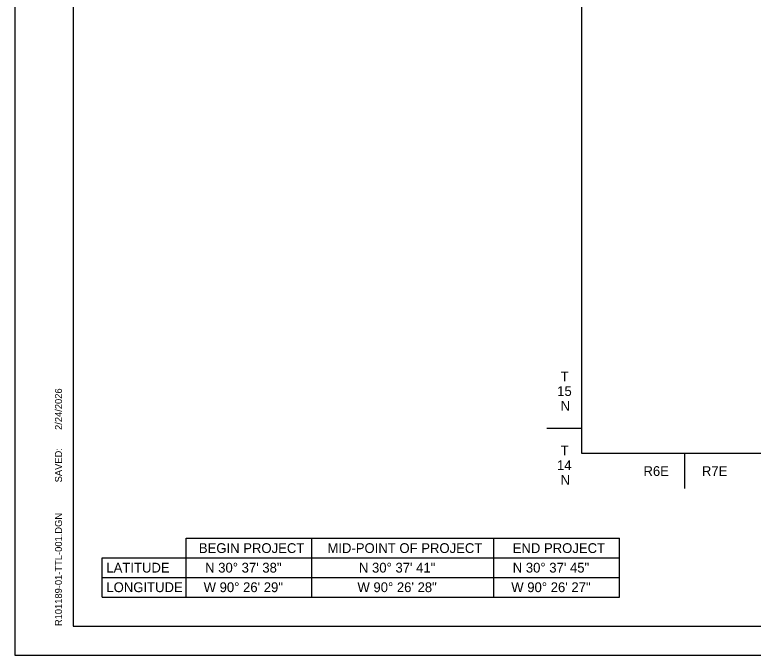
# Model space of a CAD drawing. Extents: x -0.54 to 1.64, y 0 to 0.92.
# Drawn here: x 0 to 0.528, y 0 to 0.458 of the extents above; entities that cross this region are included whole.
import ezdxf

# ---------------------------------------------------------------- set-up
doc = ezdxf.new("R2010")
doc.units = 0
for name, color, linetype in [('DSN_DRFT_DNC', 7, 'Continuous'), ('SHET_Annotations', 7, 'Continuous'), ('SHET_Border-Lines', 7, 'Continuous'), ('SHET_Border-Text', 7, 'Continuous')]:
    doc.layers.add(name, color=color, linetype=linetype)

msp = doc.modelspace()

# ---------------------------------------------------------------- linework, layer by layer
at = {"layer": 'DSN_DRFT_DNC'}
msp.add_lwpolyline([(0.4056037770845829, 0.541666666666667), (1.052729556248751, 0.541666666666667), (1.052729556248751, 0.14429633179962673), (0.4056037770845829, 0.14429633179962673)], close=True, dxfattribs=at)
at = {"layer": 'SHET_Annotations'}
for p, q in [((0.3806037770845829, 0.16250892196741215), (0.4056037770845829, 0.16250892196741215)), ((0.47890184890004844, 0.14429633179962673), (0.47890305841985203, 0.11929633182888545))]:
    msp.add_line(p, q, dxfattribs=at)
at = {"layer": 'SHET_Border-Lines'}
for points in [[(0, 0), (1.416666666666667, 0), (1.416666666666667, 0.9166666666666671), (0, 0.9166666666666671)], [(0.04166666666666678, 0.02083333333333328), (1.395833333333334, 0.02083333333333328), (1.395833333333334, 0.8958333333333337), (0.04166666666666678, 0.8958333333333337)]]:
    msp.add_lwpolyline(points, close=True, dxfattribs=at)
at = {"layer": 'SHET_Border-Text'}
for p, q in [((0.12250000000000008, 0.041666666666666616), (0.12250000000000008, 0.08366666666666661)), ((0.12250000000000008, 0.08366666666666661), (0.43250000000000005, 0.08366666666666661)), ((0.21250000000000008, 0.041666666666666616), (0.21250000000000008, 0.08366666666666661)), ((0.3425000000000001, 0.041666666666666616), (0.3425000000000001, 0.08366666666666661)), ((0.43250000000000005, 0.041666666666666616), (0.43250000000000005, 0.08366666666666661)), ((0.06250000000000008, 0.041666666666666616), (0.06250000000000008, 0.06966666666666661)), ((0.06250000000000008, 0.06966666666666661), (0.43250000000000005, 0.06966666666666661)), ((0.06250000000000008, 0.055666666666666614), (0.43250000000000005, 0.055666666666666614)), ((0.06250000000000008, 0.041666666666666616), (0.43250000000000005, 0.041666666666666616))]:
    msp.add_line(p, q, dxfattribs=at)

# ---------------------------------------------------------------- texts
at = {"layer": 'SHET_Annotations'}
for s, p in [('T', (0.3904639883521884, 0.19600892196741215)), ('15', (0.38790060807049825, 0.18550892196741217)), ('N', (0.3903062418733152, 0.17500892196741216)), ('T', (0.3904639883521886, 0.14300892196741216)), ('14', (0.3877650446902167, 0.13250892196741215)), ('R6E', (0.4495925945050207, 0.12829633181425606)), ('R7E', (0.4914024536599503, 0.12829633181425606)), ('N', (0.39030624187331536, 0.12200892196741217)), ('N 30° 37\' 38"', (0.1361199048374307, 0.05916666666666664)), ('N 30° 37\' 41"', (0.24611990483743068, 0.05916666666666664)), ('N 30° 37\' 45"', (0.3561199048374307, 0.05916666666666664)), ('W 90° 26\' 29"', (0.13506324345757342, 0.04516666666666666)), ('W 90° 26\' 28"', (0.2450632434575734, 0.04516666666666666)), ('W 90° 26\' 27"', (0.35506324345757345, 0.04516666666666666))]:
    msp.add_text(s, height=0.006999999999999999, dxfattribs=at).set_placement(p)
at = {"layer": 'SHET_Border-Text'}
for s, p in [('2/24/2026', (0.03375000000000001, 0.16122456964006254)), ('     SAVED: ', (0.03375, 0.11442879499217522)), ('R101189-01-TTL-001.DGN', (0.033749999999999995, 0.02083333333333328))]:
    msp.add_text(s, height=0.005, rotation=90, dxfattribs=at).set_placement(p)
for s, p in [('BEGIN PROJECT', (0.13165457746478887, 0.07316666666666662)), ('MID-POINT OF PROJECT', (0.2236024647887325, 0.07316666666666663)), ('END PROJECT', (0.35609612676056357, 0.07316666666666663)), ('LATITUDE', (0.06550000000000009, 0.05916666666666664)), ('LONGITUDE', (0.06550000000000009, 0.04516666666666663))]:
    msp.add_text(s, height=0.006999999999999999, dxfattribs=at).set_placement(p)

doc.saveas('drawing.dxf')
